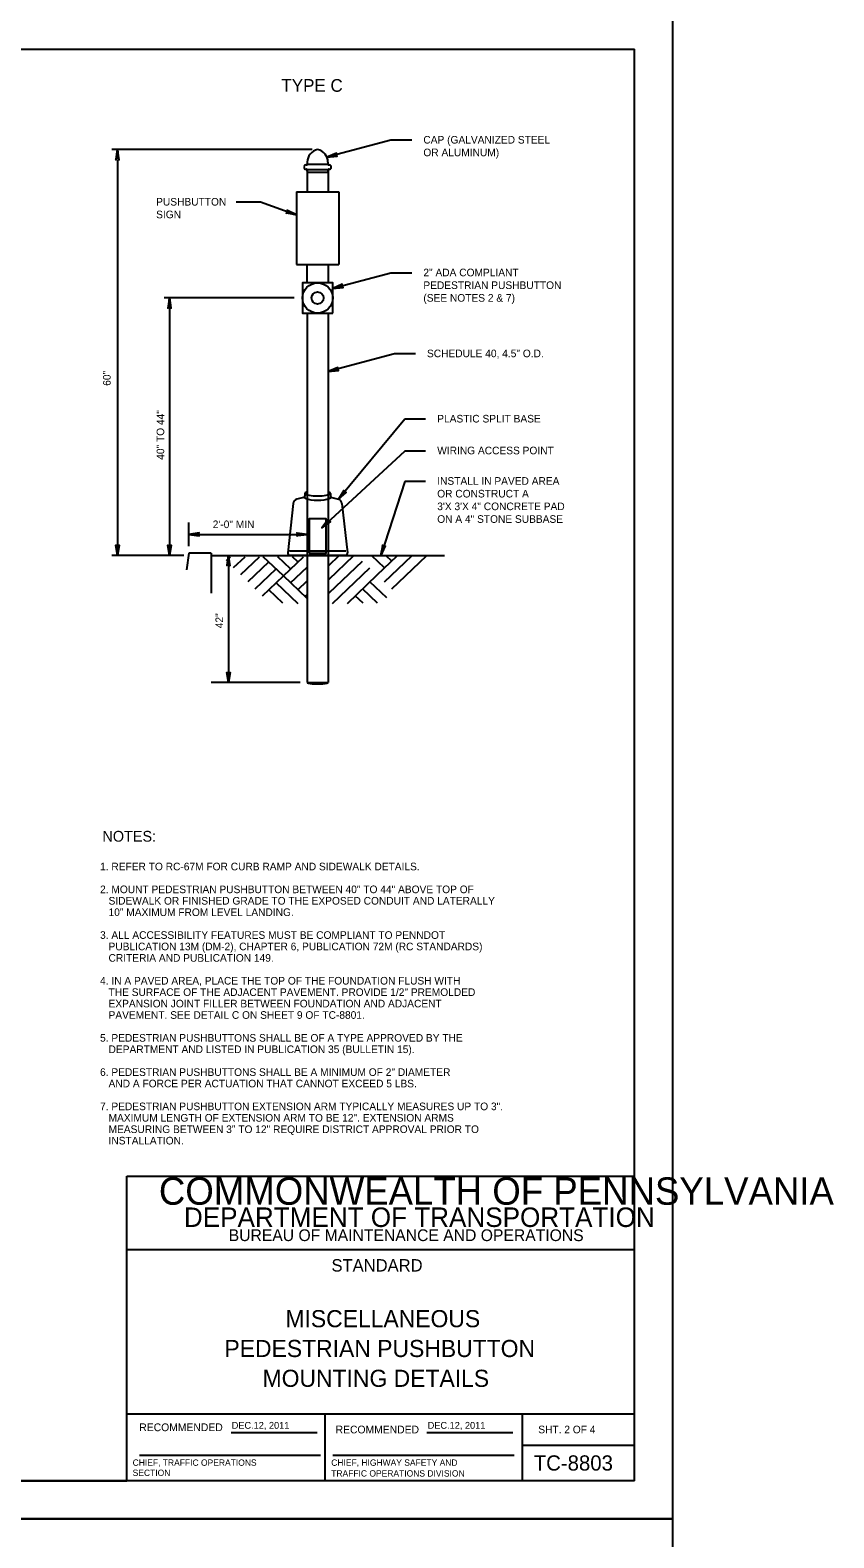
# Model space of a CAD drawing. Extents: x 36 to 940, y -1166 to 1210.
# Drawn here: x 624 to 940, y 15 to 609 of the extents above; entities that cross this region are included whole.
import ezdxf

# ---------------------------------------------------------------- set-up
doc = ezdxf.new("R2010")
doc.units = 0
for name, color, linetype in [('1', 7, 'Continuous'), ('2', 7, 'Continuous'), ('4', 7, 'Continuous'), ('Default', 7, 'Continuous'), ('Detail', 7, 'Continuous'), ('DETAILS', 7, 'Continuous'), ('PLT-BNDY', 7, 'Continuous')]:
    doc.layers.add(name, color=color, linetype=linetype)

msp = doc.modelspace()

# ---------------------------------------------------------------- linework, layer by layer
at = {"layer": '1'}
for p, q in [((75.86, 601.17), (861.86, 601.17)), ((861.86, 37.17), (861.86, 601.17)), ((765.89, 565.28), (740.64, 558.61)), ((774.1, 565.28), (765.89, 565.28)), ((704.93, 541.03), (714.44, 541.03)), ((714.44, 541.03), (728.63, 535.91)), ((765.89, 512.98), (742.95, 506.91)), ((774.1, 512.98), (765.89, 512.98)), ((767.32, 481.1), (741.15, 474.19)), ((775.52, 481.1), (767.32, 481.1)), ((771.35, 455.38), (745.19, 423.84)), ((779.56, 455.38), (771.35, 455.38)), ((771.35, 442.86), (738.64, 412.63)), ((779.56, 442.86), (771.35, 442.86)), ((771.35, 430.84), (761.87, 401.76)), ((779.56, 430.84), (771.35, 430.84)), ((686.29, 405.35), (686.29, 414.7)), ((686.29, 410.02), (732.82, 410.02)), ((661.86, 37.17), (661.86, 157.17)), ((661.86, 157.17), (861.86, 157.17)), ((861.86, 128.17), (661.86, 128.17)), ((661.86, 63.55), (861.86, 63.55)), ((739.86, 63.55), (739.86, 37.17)), ((817.73, 37.17), (817.73, 63.55)), ((702.9, 56.2), (736.82, 56.2)), ((779.99, 56.2), (813.91, 56.2)), ((817.73, 51.17), (861.86, 51.17)), ((666.74, 47.21), (738.07, 47.21)), ((742.95, 47.21), (814.41, 47.21)), ((861.86, 37.17), (75.86, 37.17)), ((75.86, 37.17), (661.86, 37.17))]:
    msp.add_line(p, q, dxfattribs=at)
for points in [[(658.58, 557.82), (658.31, 557.97), (658.11, 561.65), (658.58, 557.82), (658.75, 557.63), (658.11, 561.65), (657.92, 557.97), (657.65, 557.84), (658.11, 561.65), (657.47, 557.63), (657.65, 557.84)], [(744.23, 560.02), (744.16, 559.72), (740.64, 558.61), (744.23, 560.02), (744.37, 560.23), (740.64, 558.61), (744.25, 559.34), (744.45, 559.11), (740.64, 558.61), (744.69, 558.98), (744.45, 559.11)], [(725.16, 537.59), (725.2, 537.28), (728.63, 535.91), (725.16, 537.59), (725.03, 537.81), (728.63, 535.91), (725.08, 536.91), (724.87, 536.69), (728.63, 535.91), (724.62, 536.59), (724.87, 536.69)], [(746.54, 508.33), (746.47, 508.02), (742.95, 506.91), (746.54, 508.33), (746.69, 508.54), (742.95, 506.91), (746.56, 507.65), (746.76, 507.42), (742.95, 506.91), (747.01, 507.29), (746.76, 507.42)], [(679.14, 499.32), (678.87, 499.47), (678.66, 503.15), (679.14, 499.32), (679.31, 499.13), (678.66, 503.15), (678.48, 499.47), (678.21, 499.34), (678.66, 503.15), (678.02, 499.13), (678.21, 499.34)], [(744.74, 475.6), (744.67, 475.3), (741.15, 474.19), (744.74, 475.6), (744.89, 475.81), (741.15, 474.19), (744.76, 474.92), (744.96, 474.69), (741.15, 474.19), (745.2, 474.56), (744.96, 474.69)], [(747.29, 427.07), (747.41, 426.78), (745.19, 423.84), (747.29, 427.07), (747.29, 427.33), (745.19, 423.84), (747.7, 426.53), (748, 426.46), (745.19, 423.84), (748.27, 426.5), (748, 426.46)], [(741.11, 415.59), (741.2, 415.29), (738.64, 412.63), (741.11, 415.59), (741.14, 415.84), (738.64, 412.63), (741.46, 415), (741.74, 414.9), (738.64, 412.63), (742.02, 414.9), (741.74, 414.9)], [(690.11, 410.49), (689.97, 410.22), (686.29, 410.02), (690.11, 410.49), (690.31, 410.66), (686.29, 410.02), (689.96, 409.83), (690.1, 409.56), (686.29, 410.02), (690.3, 409.38), (690.1, 409.56)], [(728.99, 410.49), (729.14, 410.22), (732.82, 410.02), (728.99, 410.49), (728.8, 410.66), (732.82, 410.02), (729.14, 409.83), (729, 409.56), (732.82, 410.02), (728.8, 409.38), (729, 409.56)], [(658.58, 405.59), (658.31, 405.44), (658.11, 401.76), (658.58, 405.59), (658.75, 405.78), (658.11, 401.76), (657.92, 405.44), (657.65, 405.58), (658.11, 401.76), (657.47, 405.78), (657.65, 405.58)], [(679.14, 405.59), (678.87, 405.44), (678.66, 401.76), (679.14, 405.59), (679.31, 405.78), (678.66, 401.76), (678.48, 405.44), (678.21, 405.58), (678.66, 401.76), (678.02, 405.78), (678.21, 405.58)], [(762.63, 405.54), (762.85, 405.32), (761.87, 401.76), (762.63, 405.54), (762.53, 405.78), (761.87, 401.76), (763.21, 405.19), (763.51, 405.23), (761.87, 401.76), (763.75, 405.37), (763.51, 405.23)], [(702.33, 397.94), (702.05, 398.08), (701.85, 401.76), (702.33, 397.94), (702.5, 397.74), (701.85, 401.76), (701.67, 398.08), (701.4, 397.95), (701.85, 401.76), (701.21, 397.74), (701.4, 397.95)], [(702.33, 355.45), (702.05, 355.31), (701.85, 351.63), (702.33, 355.45), (702.5, 355.65), (701.85, 351.63), (701.67, 355.31), (701.4, 355.44), (701.85, 351.63), (701.21, 355.65), (701.4, 355.44)]]:
    msp.add_lwpolyline(points, dxfattribs=at)
at = {"layer": 'Default'}
for p, q in [((734.87, 561.65), (655.96, 561.65)), ((658.11, 557.41), (658.11, 401.76)), ((732.45, 555.56), (732.51, 555.56)), ((732.61, 553.87), (732.45, 553.87)), ((732.82, 553.83), (732.82, 545)), ((732.82, 553.12), (732.82, 553.67)), ((732.93, 556.69), (732.93, 555.95)), ((733.23, 552.72), (740.74, 552.72)), ((741.04, 556.69), (741.04, 555.95)), ((741.15, 553.83), (741.15, 545)), ((741.15, 553.12), (741.15, 553.67)), ((741.52, 553.87), (741.36, 553.87)), ((741.46, 555.56), (741.52, 555.56)), ((742.35, 554.66), (742.35, 554.76)), ((728.63, 545), (745.34, 545)), ((728.63, 545), (728.63, 516.35)), ((745.34, 545), (745.34, 516.35)), ((728.63, 516.35), (745.34, 516.35)), ((732.82, 509.12), (732.82, 516.35)), ((741.15, 516.35), (741.15, 509.12)), ((727.79, 503.15), (676.51, 503.15)), ((678.66, 503.15), (678.66, 401.76)), ((731.02, 497.18), (742.95, 497.18)), ((732.82, 497.18), (732.82, 351.63)), ((741.15, 497.18), (741.15, 351.63)), ((727.4, 422.15), (725.2, 402.78)), ((731.42, 424.49), (728.78, 423.84)), ((731.93, 426.15), (731.93, 425.1)), ((742.04, 426.15), (742.04, 425.1)), ((742.54, 424.49), (745.19, 423.84)), ((746.57, 422.15), (748.76, 402.78)), ((684.25, 401.76), (655.96, 401.76)), ((695, 401.76), (786.97, 401.76)), ((701.06, 399.7), (702.65, 401.22)), ((701.85, 401.76), (701.85, 351.63)), ((703.89, 396.93), (708.4, 401.22)), ((706.73, 394.16), (714.14, 401.22)), ((709.56, 391.39), (717.74, 399.17)), ((723.48, 393.7), (715.59, 401.22)), ((726.35, 396.44), (721.33, 401.22)), ((723.48, 393.7), (731.38, 401.22)), ((725.87, 403.54), (748.09, 403.54)), ((726.01, 401.82), (747.95, 401.82)), ((729.23, 399.17), (727.08, 401.22)), ((741.5, 392.4), (751.12, 401.56)), ((741.5, 397.87), (745.37, 401.56)), ((741.5, 386.93), (754.71, 399.51)), ((763.33, 396.77), (758.31, 401.56)), ((760.46, 394.04), (768.35, 401.56)), ((763.33, 391.3), (774.1, 401.56)), ((766.2, 399.51), (764.05, 401.56)), ((766.2, 388.57), (779.84, 401.56)), ((712.39, 388.61), (720.61, 396.44)), ((715.23, 385.84), (723.48, 393.7)), ((732.84, 384.79), (723.48, 393.7)), ((726.35, 390.97), (732.84, 397.15)), ((742.91, 382.79), (757.59, 396.77)), ((748.7, 382.84), (760.46, 394.04)), ((723.34, 382.9), (717.74, 388.23)), ((729.38, 382.61), (720.61, 390.97)), ((729.23, 388.23), (732.84, 391.68)), ((732.1, 385.5), (732.84, 386.2)), ((760.63, 382.93), (754.71, 388.57)), ((764.22, 384.99), (757.59, 391.3)), ((749.24, 382.84), (748.97, 383.1)), ((754.93, 382.89), (751.84, 385.83)), ((730.14, 351.63), (695.03, 351.63)), ((732.82, 351.63), (741.15, 351.63))]:
    msp.add_line(p, q, dxfattribs=at)
msp.add_lwpolyline([(742.95, 497.18), (742.95, 509.12), (731.02, 509.12), (731.02, 497.18), (731.02, 497.18)], dxfattribs=at)
for radius in [5.97, 2.39]:
    msp.add_circle((736.98, 503.15), radius, dxfattribs=at)
for centre, major_axis, ratio, start_param, end_param in [((738.35, 556.65), (5.43, 0), 0.952381, 1.825494, 3.132766), ((735.62, 556.65), (5.43, 0), 0.952381, 0.008827, 1.316099), ((732.45, 554.76), (0.833, 0), 0.952381, 1.570796, 3.141593), ((732.45, 554.66), (0.833, 0), 0.952381, 3.141593, 4.712389), ((732.51, 555.95), (0.417, 0), 0.952381, 4.712389, 6.283185), ((732.61, 553.67), (0.208, 0), 0.952381, 0, 1.570796), ((737.06, 553.87), (-4.46, 0), 0.026054, 0.212556, 2.780907), ((733.23, 553.12), (0.417, 0), 0.952381, 3.141593, 4.712389), ((736.98, 555.95), (-4.06, 0), 0.012269, 0, 3.141593), ((740.74, 553.12), (0.417, 0), 0.952381, 4.712389, 6.283185), ((741.46, 555.95), (0.417, 0), 0.952381, 3.141593, 4.712389), ((741.36, 553.67), (0.208, 0), 0.952381, 1.570796, 3.141593), ((741.52, 554.76), (0.833, 0), 0.952381, 0, 1.570796), ((741.52, 554.66), (0.833, 0), 0.952381, 4.712389, 6.283185), ((729.23, 422.15), (1.83, 0), 0.952381, 1.821847, 3.141593), ((736.98, 426.15), (-5.06, 0), 0.197066, 5.681211, 10.026837), ((731.26, 425.1), (0.667, 0), 0.952381, 4.96344, 6.283185), ((736.98, 424.71), (-5.2, 0), 0.23546, 6.283185, 9.424778), ((742.7, 425.1), (0.667, 0), 0.952381, 3.141593, 4.461338), ((744.73, 422.15), (1.83, 0), 0.952381, 0, 1.319746), ((726.01, 402.62), (0.833, 0), 0.952381, 2.933403, 4.712389), ((747.95, 402.62), (0.833, 0), 0.952381, 4.712389, 6.491374), ((736.98, 351.63), (-4.17, 0), 0.122994, 6.282432, 9.425531)]:
    msp.add_ellipse(centre, major_axis=major_axis, ratio=ratio, start_param=start_param, end_param=end_param, dxfattribs=at)
at = {"layer": 'Detail'}
msp.add_lwpolyline([(733.71, 402.64), (740.33, 402.64), (740.33, 416.2), (733.71, 416.2)], close=True, dxfattribs=at)
at = {"layer": 'DETAILS'}
for p, q in [((686.29, 402.58), (685.35, 396.05)), ((695, 402.58), (686.29, 402.58)), ((695, 402.58), (695, 400.95)), ((695, 400.95), (695, 386.79))]:
    msp.add_line(p, q, dxfattribs=at)
at = {"layer": 'PLT-BNDY'}
for points in [[(35.86, 616.17), (876.86, 616.17), (876.86, 22.17), (35.86, 22.17)], [(35.86, 22.17), (876.86, 22.17), (876.86, -571.83), (35.86, -571.83)]]:
    msp.add_lwpolyline(points, close=True, dxfattribs=at)

# ---------------------------------------------------------------- texts
at = {"layer": '1'}
for s, height, p in [('COMMONWEALTH OF PENNSYLVANIA', 10.7828, (674.45, 145.9)), ('DEPARTMENT OF TRANSPORTATION', 7.6837, (684.31, 137.15)), ('BUREAU OF MAINTENANCE AND OPERATIONS', 4.6253, (701.95, 131.59)), ('MISCELLANEOUS', 6.75, (724.3, 97.65)), ('PEDESTRIAN PUSHBUTTON', 6.75, (700.28, 85.9)), ('MOUNTING DETAILS', 6.75, (715.3, 74.15)), ('RECOMMENDED', 3.0516, (666.73, 56.7)), ('RECOMMENDED', 3.0516, (744.08, 55.82)), ('SHT. 2 OF 4', 3, (823.94, 55.86)), ('TC-8803', 6, (822.14, 41.17))]:
    msp.add_text(s, height=height, dxfattribs=at).set_placement(p)
at = {"layer": '2'}
for s, height, p in [('TYPE C', 5, (722.73, 584.39)), ('CAP (GALVANIZED STEEL', 3, (778.66, 563.99)), ('OR ALUMINUM)', 3, (778.66, 558.99)), ('PUSHBUTTON', 3, (673.36, 539.56)), ('SIGN', 3, (673.36, 534.56)), ('2" ADA COMPLIANT', 3, (778.66, 511.69)), ('PEDESTRIAN PUSHBUTTON', 3, (778.66, 506.69)), ('(SEE NOTES 2 & 7)', 3, (778.66, 501.69)), ('SCHEDULE 40, 4.5" O.D.', 3, (780.08, 479.81)), ('PLASTIC SPLIT BASE', 3, (784.12, 454.1)), ('WIRING ACCESS POINT', 3, (784.12, 441.57)), ('INSTALL IN PAVED AREA  ', 3, (784.12, 429.56)), ('3\'X 3\'X 4" CONCRETE PAD ', 3, (784.12, 419.56)), ('OR CONSTRUCT A ', 3, (784.12, 424.56)), ('ON A 4" STONE SUBBASE', 3, (784.12, 414.56)), ('2\'-0" MIN', 3, (695.65, 412.48)), ('NOTES:', 4.25, (652.19, 288.95)), ('1. REFER TO RC-67M FOR CURB RAMP AND SIDEWALK DETAILS.', 3, (651.26, 277.66)), ('2. MOUNT PEDESTRIAN PUSHBUTTON BETWEEN 40" TO 44" ABOVE TOP OF ', 3, (651.26, 268.66)), ('   SIDEWALK OR FINISHED GRADE TO THE EXPOSED CONDUIT AND LATERALLY  ', 3, (651.26, 264.16)), ('   10" MAXIMUM FROM LEVEL LANDING.', 3, (651.26, 259.66)), ('3. ALL ACCESSIBILITY FEATURES MUST BE COMPLIANT TO PENNDOT ', 3, (651.26, 250.66)), ('   CRITERIA AND PUBLICATION 149.', 3, (651.26, 241.66)), ('   PUBLICATION 13M (DM-2), CHAPTER 6, PUBLICATION 72M (RC STANDARDS)', 3, (651.26, 246.16)), ('4. IN A PAVED AREA, PLACE THE TOP OF THE FOUNDATION FLUSH WITH', 3, (651.26, 232.66)), ('   THE SURFACE OF THE ADJACENT PAVEMENT. PROVIDE 1/2" PREMOLDED', 3, (651.26, 228.16)), ('   EXPANSION JOINT FILLER BETWEEN FOUNDATION AND ADJACENT ', 3, (651.26, 223.66)), ('   PAVEMENT. SEE DETAIL C ON SHEET 9 OF TC-8801.', 3, (651.26, 219.16)), ('5. PEDESTRIAN PUSHBUTTONS SHALL BE OF A TYPE APPROVED BY THE', 3, (651.26, 210.16)), ('   DEPARTMENT AND LISTED IN PUBLICATION 35 (BULLETIN 15).', 3, (651.26, 205.66)), ('6. PEDESTRIAN PUSHBUTTONS SHALL BE A MINIMUM OF 2" DIAMETER', 3, (651.26, 196.66)), ('   AND A FORCE PER ACTUATION THAT CANNOT EXCEED 5 LBS.', 3, (651.26, 192.16)), ('7. PEDESTRIAN PUSHBUTTON EXTENSION ARM TYPICALLY MEASURES UP TO 3".', 3, (651.26, 183.16)), ('   MAXIMUM LENGTH OF EXTENSION ARM TO BE 12". EXTENSION ARMS ', 3, (651.26, 178.66)), ('   MEASURING BETWEEN 3" TO 12" REQUIRE DISTRICT APPROVAL PRIOR TO ', 3, (651.26, 174.16)), ('   INSTALLATION.', 3, (651.26, 169.66)), ('DEC.12, 2011', 2.7032, (703.15, 57.64))]:
    msp.add_text(s, height=height, dxfattribs=at).set_placement(p)
for s, height, rotation, p in [('  60"', 3, 90, (655.44, 466.33)), ('40" TO 44"', 3, 90, (676.55, 439.4)), ('42"', 3, 90, (699.74, 373.03)), ('DEC.12, 2011', 2.7032, 360, (780.37, 57.64))]:
    msp.add_text(s, height=height, rotation=rotation, dxfattribs=at).set_placement(p)
at = {"layer": '4'}
msp.add_text('STANDARD', height=4.881, rotation=360, dxfattribs=at).set_placement((742.45, 119.59))
at = {"layer": 'Default'}
for s, p in [('SECTION', (664.1, 39.06)), ('CHIEF, TRAFFIC OPERATIONS', (664.1, 43.06)), ('CHIEF, HIGHWAY SAFETY AND', (742.35, 43.06)), ('TRAFFIC OPERATIONS DIVISION', (742.35, 38.81))]:
    msp.add_text(s, height=2.5, dxfattribs=at).set_placement(p)

doc.saveas('drawing.dxf')
